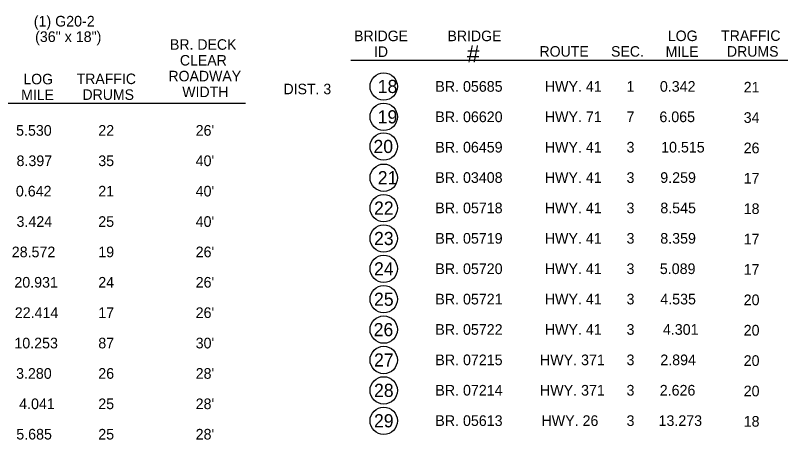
# Model space of a CAD drawing. Extents: x 1927831 to 1930787, y 596452 to 597699.
# Drawn here: x 1928053.9 to 1928485.3, y 596678 to 596917.1 of the extents above; entities that cross this region are included whole.
import ezdxf

# ---------------------------------------------------------------- set-up
doc = ezdxf.new("R2010")
doc.units = 0
doc.layers.add('Default', color=7, linetype='Continuous')
doc.layers.add('R_Annotation', color=7, linetype='Continuous')

msp = doc.modelspace()

# ---------------------------------------------------------------- linework, layer by layer
at = {"layer": 'Default'}
for centre in [(1928261.52, 596877.08), (1928261.52, 596877.08), (1928261.52, 596859.96), (1928261.52, 596843.27), (1928261.52, 596825.65), (1928261.52, 596808.53), (1928261.52, 596791.41), (1928261.52, 596774.3), (1928261.52, 596757.18), (1928261.52, 596740.06), (1928261.52, 596722.94), (1928261.52, 596705.83), (1928261.52, 596688.71)]:
    msp.add_circle(centre, 7.71, dxfattribs=at)
at = {"layer": 'R_Annotation'}
for p, q in [((1928242.96, 596891.91), (1928546.89, 596891.91)), ((1927879.74, 596867.56), (1928183.67, 596867.56))]:
    msp.add_line(p, q, dxfattribs=at)

# ---------------------------------------------------------------- texts
for s, height, p in [('(1) G20-2', 6, (1928064.32, 596910.83)), ('(36" x 18")', 5.9996, (1928065.06, 596902.11))]:
    msp.add_text(s, height=height, dxfattribs=at).set_placement(p)
for s, height, p in [('BRIDGE ', 5.929, (1928244.85, 596902.58)), ('BRIDGE ', 5.929, (1928297.48, 596902.58)), ('LOG', 5.929, (1928421.67, 596902.62)), ('TRAFFIC ', 5.929, (1928451.68, 596902.74)), ('BR. DECK ', 5.929, (1928141.09, 596897.74)), ('ID', 5.929, (1928256.03, 596893.69)), ('#', 9.5, (1928308.47, 596890.71)), ('ROUTE', 5.929, (1928349.33, 596893.85)), ('SEC.', 5.929, (1928389.66, 596893.85)), ('MILE', 5.929, (1928420.43, 596893.73)), ('DRUMS', 5.929, (1928454.97, 596893.85)), ('CLEAR', 5.929, (1928146.67, 596888.84)), ('ROADWAY ', 5.929, (1928140.21, 596879.95)), ('LOG', 5.929, (1928058.45, 596878.27)), ('TRAFFIC ', 5.929, (1928088.45, 596878.39)), ('DIST. 3', 5.929, (1928205.05, 596872.67)), ('18', 7.412, (1928258.19, 596873.37)), ('BR. 05685', 6, (1928290.61, 596874.08)), ('HWY. 41', 6, (1928352.29, 596874.08)), ('1', 6, (1928398.39, 596874.08)), ('0.342', 6, (1928417.18, 596874.08)), ('21', 6, (1928464.4, 596873.66)), ('MILE', 5.929, (1928057.21, 596869.37)), ('DRUMS', 5.929, (1928091.74, 596869.5)), ('WIDTH', 5.929, (1928148, 596871.05)), ('19', 7.412, (1928258.16, 596856.25)), ('BR. 06620', 6, (1928290.61, 596856.96)), ('HWY. 71', 6, (1928352.29, 596856.96)), ('7', 6, (1928398.39, 596856.96)), ('6.065', 6, (1928416.9, 596856.96)), ('34', 6, (1928464.4, 596856.54)), ('5.530', 6, (1928054.34, 596849.3)), ('22', 6, (1928100.67, 596849.3)), ("26'", 6, (1928155.55, 596849.3)), ('20', 7.412, (1928255.77, 596839.56)), ('BR. 06459', 6, (1928290.61, 596839.84)), ('HWY. 41', 6, (1928352.29, 596839.84)), ('3', 6, (1928398.39, 596839.84)), ('10.515', 6, (1928417.89, 596839.84)), ('26', 6, (1928464.4, 596839.42)), ('8.397', 6, (1928054.6, 596832.19)), ('35', 6, (1928100.67, 596832.19)), ("40'", 6, (1928155.55, 596832.19)), ('21', 7.412, (1928258.19, 596821.94)), ('BR. 03408', 6, (1928290.61, 596822.73)), ('HWY. 41', 6, (1928352.29, 596822.73)), ('3', 6, (1928398.39, 596822.73)), ('9.259', 6, (1928417.4, 596822.73)), ('17', 6, (1928464.4, 596822.3)), ('0.642', 6, (1928054.23, 596815.07)), ('21', 6, (1928100.67, 596815.07)), ("40'", 6, (1928155.55, 596815.07)), ('22', 7.412, (1928256.09, 596804.83)), ('BR. 05718', 6, (1928290.61, 596805.61)), ('HWY. 41', 6, (1928352.29, 596805.61)), ('3', 6, (1928398.39, 596805.61)), ('8.545', 6, (1928417.42, 596805.61)), ('18', 6, (1928464.4, 596805.19)), ('3.424', 6, (1928054.6, 596797.95)), ('25', 6, (1928100.67, 596797.95)), ("40'", 6, (1928155.55, 596797.95)), ('23', 7.412, (1928256.09, 596787.71)), ('BR. 05719', 6, (1928290.61, 596788.49)), ('HWY. 41', 6, (1928352.29, 596788.49)), ('3', 6, (1928398.39, 596788.49)), ('8.359', 6, (1928417.4, 596788.49)), ('17', 6, (1928464.4, 596788.07)), ('28.572', 6, (1928051.91, 596780.83)), ('19', 6, (1928100.67, 596780.83)), ("26'", 6, (1928155.55, 596780.83)), ('24', 7.412, (1928256.09, 596770.59)), ('BR. 05720', 6, (1928290.61, 596771.37)), ('HWY. 41', 6, (1928352.29, 596771.37)), ('3', 6, (1928398.39, 596771.37)), ('5.089', 6, (1928417.16, 596771.37)), ('17', 6, (1928464.4, 596770.95)), ('20.931', 6, (1928053.37, 596763.72)), ('24', 6, (1928100.67, 596763.72)), ("26'", 6, (1928155.55, 596763.72)), ('25', 7.412, (1928256.09, 596753.47)), ('BR. 05721', 6, (1928290.61, 596754.25)), ('HWY. 41', 6, (1928352.29, 596754.25)), ('3', 6, (1928398.39, 596754.25)), ('4.535', 6, (1928417.42, 596754.25)), ('20', 6, (1928464.4, 596753.83)), ('22.414', 6, (1928053.61, 596746.6)), ('17', 6, (1928100.67, 596746.6)), ("26'", 6, (1928155.55, 596746.6)), ('26', 7.412, (1928255.89, 596736.36)), ('BR. 05722', 6, (1928290.61, 596737.14)), ('HWY. 41', 6, (1928352.29, 596737.14)), ('3', 6, (1928398.39, 596737.14)), ('4.301', 6, (1928418.88, 596737.14)), ('20', 6, (1928464.4, 596736.72)), ('10.253', 6, (1928053.37, 596729.48)), ('87', 6, (1928100.67, 596729.48)), ("30'", 6, (1928155.55, 596729.48)), ('27', 7.412, (1928256.09, 596719.24)), ('BR. 07215', 6, (1928290.61, 596720.02)), ('HWY. 371', 6, (1928349.59, 596720.02)), ('3', 6, (1928398.39, 596720.02)), ('2.894', 6, (1928417.42, 596720.02)), ('20', 6, (1928464.4, 596719.6)), ('3.280', 6, (1928054.34, 596712.36)), ('26', 6, (1928100.67, 596712.36)), ("28'", 6, (1928155.55, 596712.36)), ('28', 7.412, (1928256.09, 596702.12)), ('BR. 07214', 6, (1928290.61, 596702.9)), ('HWY. 371', 6, (1928349.59, 596702.9)), ('3', 6, (1928398.39, 596702.9)), ('2.626', 6, (1928417.11, 596702.9)), ('20', 6, (1928464.4, 596702.48)), ('4.041', 6, (1928056.07, 596695.25)), ('25', 6, (1928100.67, 596695.25)), ("28'", 6, (1928155.55, 596695.25)), ('29', 7.412, (1928256.06, 596685)), ('BR. 05613', 6, (1928290.61, 596685.78)), ('HWY. 26', 6, (1928350.42, 596685.78)), ('3', 6, (1928398.39, 596685.78)), ('13.273', 6, (1928416.43, 596685.78)), ('18', 6, (1928464.4, 596685.36)), ('5.685', 6, (1928054.46, 596678.13)), ('25', 6, (1928100.67, 596678.13)), ("28'", 6, (1928155.55, 596678.13))]:
    msp.add_text(s, height=height, rotation=360, dxfattribs=at).set_placement(p)

doc.saveas('drawing.dxf')
